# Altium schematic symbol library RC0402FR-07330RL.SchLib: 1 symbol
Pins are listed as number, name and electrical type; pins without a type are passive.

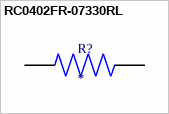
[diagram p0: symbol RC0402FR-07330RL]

## RC0402FR-07330RL
designator R?
330 Ohms Â±1% 0.063W, 1/16W Chip Resistor 0402 (1005 Metric) Moisture Resistant Thick Film; MF: Yageo; MP: RC0402FR-07330RL
footprint RESC1005X40N
pins: 1, 2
